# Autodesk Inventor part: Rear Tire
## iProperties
Shininess: 20.0
Angle Display Precision: 2
Document Length Units: 11269
Document Angle Units: 11279
Document Time Units: 11290
Document Mass Units: 11283
Document Length Units Precision: 3
Document Angle Units Precision: 2
Compacted: True
Created: 2001-08
Part Number: Rear Tire
Document SubType Name: Modeling
Designer: Martin Budgell
Density: 0.0
Volumn: 0.0
Area: 0.0
PropertySet Name: Model Information
Control State: 0
Master: False
Checked Out: False
Author: Martin Budgell
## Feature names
1. Revolution1
2. Extrusion1
3. Circular Pattern1
